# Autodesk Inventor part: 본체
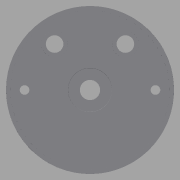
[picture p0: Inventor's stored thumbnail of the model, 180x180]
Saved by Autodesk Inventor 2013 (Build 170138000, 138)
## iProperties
Created: 2015-04
Part Number: 본체
Material: 일반
Document SubType Name: Modeling
Designer: WINDOWS7
Density: 1 g/cm^3
Author: WINDOWS7
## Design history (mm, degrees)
sketch "스케치1"
  geometry: C1 r 95 at (0, 0); 1 further point
  constraints: 1 centre point, 1 coincident
  dimensions: "d0" = 190 diameter of C1
extrude "돌출1" new body sketch "스케치1" distance "d1" = 32; taper "d2" = 0 deg
sketch "스케치2"
  geometry: L1 (0, 0)-(95, 0); L2 (0, 0)-(94.638, -8.28); L3 (0, 0)-(0, -95); L4 (0, 0)-(-94.638, -8.28); A1 r 95 centre (0, 0) between (95, 0) and (0, -95) reference; A2 r 95 centre (0, 0) between (-94.638, -8.28) and (94.638, -8.28)
  constraints: 8 end point, 6 point on circle, 1 centre point, 1 coincident, 1 horizontal, 1 perpendicular, 1 symmetric about line
  dimensions: "d3" = 5 deg angle of L1 L2
extrude "돌출2" cut sketch "스케치2" distance "d4" = 5; taper "d5" = 0 deg; dims "d15" = 180
sketch "스케치3"
  geometry: L1 (0, 0)-(-95, 0); L2 (0, 0)-(-50.912, 50.912); L3 (0, 0)-(0, 95); L4 (0, 0)-(50.912, 50.912); L5 (36.062, 36.062)-(50.912, 50.912); L6 (-36.062, 36.062)-(-50.912, 50.912); A1 r 95 centre (0, 0) between (-95, 0) and (0, 95) reference; A2 r 51 centre (0, 0) between (36.062, 36.062) and (-36.062, 36.062); A3 r 72 centre (0, 0) between (50.912, 50.912) and (-50.912, 50.912)
  constraints: 12 end point, 6 point on circle, 2 centre point, 2 coincident, 2 point on line, 1 collinear, 1 horizontal, 1 perpendicular, 1 symmetric about line
  dimensions: "d8" = 51 radius of A2; "d10" = 72 radius of A3; "d11" = 90 deg angle of L2 L4
extrude "돌출3" join sketch "스케치3" distance "d12" = 5.5; taper "d13" = 0 deg
fillet "모깎기1" dims "d14" = 5
sketch "스케치4"
  geometry: L1 (0, 0)-(100.649, 0); L2 (-89.196, 12)-(-40.249, 12); L3 (40.249, 12)-(89.196, 12); A1 r 95 centre (0, 0) between (94.638, -8.28) and (-94.638, -8.28) reference; A2 r 42 centre (0, 0) between (40.249, 12) and (-40.249, 12); A3 r 90 centre (0, 0) between (89.196, 12) and (-89.196, 12)
  constraints: 6 end point, 4 point on circle, 2 centre point, 2 coincident, 2 parallel, 1 horizontal
  dimensions: "d50" = 12 distance between parallel lines of L3 L1; "d52" = 42 radius of A2; "d54" = 90 radius of A3; "d55" = 12 distance between parallel lines of L1 L2
extrude "돌출9" cut sketch "스케치4" distance "d56" = 25; taper "d57" = 0 deg
fillet "모깎기2" dims "d58" = 10
sketch "스케치7"
  geometry: L1 (-47.117, 12)-(-76.916, 12) reference; L2 (76.916, 12)-(47.117, 12) reference; C1 r 90 at (0, 0); A1 r 42 centre (0, 0) between (38.056, 17.769) and (-38.056, 17.769) reference; A2 r 10 centre (-47.117, 22) between (-47.117, 12) and (-38.056, 17.769) reference; A3 r 10 centre (-76.916, 22) between (-86.53, 24.75) and (-76.916, 12) reference; A4 r 90 centre (0, 0) between (86.53, 24.75) and (-86.53, 24.75) reference; A5 r 10 centre (76.916, 22) between (76.916, 12) and (86.53, 24.75) reference; A6 r 10 centre (47.117, 22) between (38.056, 17.769) and (47.117, 12) reference; A7 r 95 centre (0, 0) between (94.638, -8.28) and (-94.638, -8.28) reference
  constraints: 1 centre point, 1 coincident
  dimensions: "d59" = 180 diameter of C1
extrude "돌출10" cut sketch "스케치7" distance "d61" = 18; taper "d62" = 0 deg
sketch "스케치8"
  geometry: L1 (47.117, 12)-(76.916, 12) reference; L2 (-76.916, 12)-(-47.117, 12) reference; L3 (0, 0)-(0, -49.147); L4 (0, 0)-(49.869, 0); L5 (-59, -19)-(-41, -19); L6 (41, -19)-(59, -19); L7 (-59, -14)-(-41, -14); L8 (-59, -19)-(-59, -14); L9 (-41, -19)-(-41, -14); L10 (41, -19)-(41, -14); L11 (59, -19)-(59, -14); L12 (59, -14)-(41, -14); A1 r 42 centre (0, 0) between (38.056, 17.769) and (-38.056, 17.769) reference; A2 r 59 centre (0, -19) between (-59, -19) and (59, -19); A3 r 41 centre (0, -19) between (-41, -19) and (41, -19); A4 r 9 centre (-50, -14) between (-41, -14) and (-59, -14); A5 r 9 centre (50, -14) between (59, -14) and (41, -14)
  constraints: 20 end point, 8 point on circle, 7 parallel, 4 centre point, 3 perpendicular, 3 symmetric about line, 2 coincident, 2 tangent, 1 midpoint, 1 point on line, 1 other
  dimensions: "d75" = 118 diameter of A2; "d76" = 82 diameter of A3; "d79" = 19 distance between parallel lines of L4 L6; "d116" = 5 distance between parallel lines of L6 L12
extrude "돌출11" cut sketch "스케치8" distance "d81" = 7; taper "d82" = 0 deg
sketch "스케치9"
  geometry: C1 r 95 at (0, 0) reference; C2 r 11.5 at (0, 0)
  constraints: 1 centre point, 1 coincident
  dimensions: "d83" = 23 diameter of C2
extrude "돌출12" cut sketch "스케치9" stored distance "d85" = 7; taper "d86" = 0 deg
sketch "스케치10"
  geometry: C1 r 25 at (0, 0); A1 r 95 centre (0, 0) between (94.638, -8.28) and (-94.638, -8.28) reference
  constraints: 1 centre point, 1 coincident
  dimensions: "d87" = 50 diameter of C1
extrude "돌출13" cut sketch "스케치10" distance "d89" = 25; taper "d90" = 0 deg
fillet "모깎기3" dims "d91" = 1
fillet "모깎기4" dims "d92" = 0.3
sketch "스케치11"
  geometry: L1 (0, 0)-(0, 90); C1 r 10 at (-40, 52); C2 r 15 at (-40, 52); C3 r 15 at (40, 52); C4 r 10 at (40, 52); A1 r 90 centre (0, 0) between (86.53, 24.75) and (-86.53, 24.75) reference; A2 r 42 centre (0, 0) between (38.056, 17.769) and (-38.056, 17.769) reference
  constraints: 4 centre point, 2 coincident, 2 end point, 2 symmetric about line, 1 point on circle, 2 other
  dimensions: "d93" = 80 distance of C3.centre C1.centre; "d95" = 20 diameter of C4; "d96" = 30 diameter of C3; "d97" = 52 vertical distance of C1.centre A1.centre
extrude "돌출14" join sketch "스케치11" distance "d98" = 25; taper "d99" = 0 deg
sketch "스케치12"
  geometry: L1 (-49.658, -59.844)-(-54.638, -60.28) reference; L2 (134.638, -60.28)-(129.658, -59.844) reference; L3 (0, 0)-(0, 19.2); L4 (-6, 13.748)-(-6, -13.748); L5 (6, 13.748)-(6, -13.748); C1 r 10 at (0, 0) reference; C2 r 10 at (80, 0) reference; C3 r 15 at (80, 0) reference; A1 r 15 centre (0, 0) between (6, 13.748) and (-6, 13.748) reference; A2 r 95 centre (40, -52) between (134.638, -60.28) and (-54.638, -60.28) reference; A3 r 90 centre (40, -52) between (129.658, -59.844) and (-49.658, -59.844) reference; 1 further point
  constraints: 6 end point, 4 point on circle, 1 parallel, 1 vertical
  dimensions: "d100" = 12 distance between parallel lines of L4 L5
extrude "돌출15" cut sketch "스케치12" distance "d102" = 3; taper "d103" = 0 deg
fillet "모깎기5" dims "d104" = 3
sketch "스케치13"
  geometry: L1 (99, -71)-(99, -66) reference; L2 (81, -66)-(81, -71) reference; L3 (-1, -71)-(-1, -66) reference; L4 (-19, -66)-(-19, -71) reference; L5 (87.117, -40)-(116.916, -40) reference; L6 (-36.916, -40)-(-7.117, -40) reference; C1 r 10 at (0, 0) reference; C2 r 15 at (80, 0) reference; C3 r 10 at (0, 0) reference; C4 r 15 at (0, 0) reference; C5 r 10 at (80, 0) reference; C6 r 24.7 at (40, -52) reference; C7 r 11.5 at (40, -52) reference; C8 r 95 at (40, -52) reference; A1 r 9 centre (90, -66) between (99, -66) and (81, -66) reference; A2 r 41 centre (40, -71) between (-1, -71) and (81, -71) reference; A3 r 9 centre (-10, -66) between (-1, -66) and (-19, -66) reference; A4 r 59 centre (40, -71) between (-19, -71) and (99, -71) reference; A5 r 10 centre (87.117, -30) between (78.056, -34.231) and (87.117, -40) reference; A6 r 10 centre (116.916, -30) between (116.916, -40) and (126.53, -27.25) reference; A7 r 90 centre (40, -52) between (126.53, -27.25) and (-46.53, -27.25) reference; A8 r 10 centre (-36.916, -30) between (-46.53, -27.25) and (-36.916, -40) reference; A9 r 10 centre (-7.117, -30) between (-7.117, -40) and (1.944, -34.231) reference; A10 r 42 centre (40, -52) between (78.056, -34.231) and (1.944, -34.231) reference; 1 further point
extrude "돌출16" cut sketch "스케치13" stored distance "d105" = 3; taper "d106" = 0 deg
sketch "스케치14"
  geometry: L1 (0, 0)-(-95, 0); L2 (0, 0)-(0, -95); A1 r 95 centre (0, 0) between (-95, 0) and (0, -95) reference; A2 r 75 centre (0, 0) between (48.927, 56.843) and (-48.927, 56.843) reference; 2 further points
  constraints: 4 end point, 2 point on circle, 1 horizontal, 1 perpendicular, 1 point on line, 1 symmetric about line
  dimensions: "d107" = 148 distance of point (-74, 0) point (74, 0)
hole "구멍1" sketch "스케치14" at (-74, 0), (74, 0) diameter "d109" = 11; stored, may be unused: countersink angle "d113" = 90 deg, drill point angle "d115" = 118 deg; dims "d110" = 6, "d111" = 18, "d112" = 11, "d114" = 8
fillet "모깎기6" dims "d117" = 5
node "솔리드1"
mirror "대칭1"
node "절단 모서리 투영1"
node "절단 모서리 투영2"
other parameters: "d36" = 84, "d48" = 84, "d49" = 12, "d65" = 19, "d77" = 12
